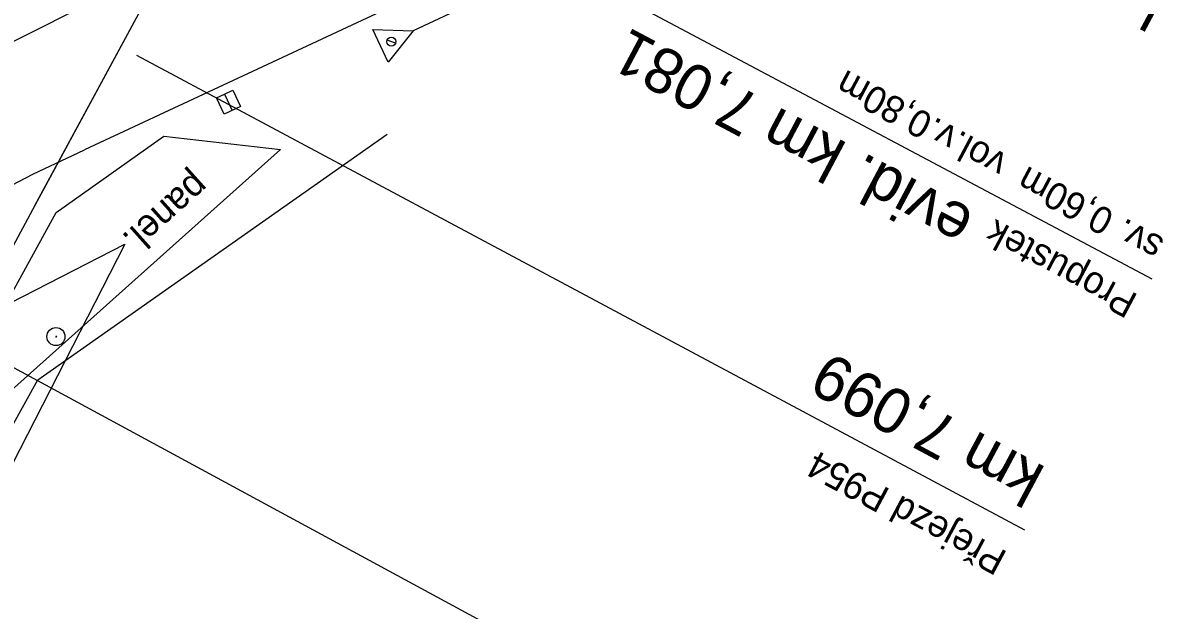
# Model space of a CAD drawing. Extents: x -795094 to -794639, y -1135368 to -1134681.
# Drawn here: x -794897.6 to -794834.2, y -1135065.2 to -1135032.7 of the extents above; entities that cross this region are included whole.
import ezdxf

# ---------------------------------------------------------------- set-up
doc = ezdxf.new("R2010")
doc.units = 0
for name, color, linetype in [('0381KM005-009P - Vrstva 1', 7, 'Continuous'), ('0381KM005-009P - Vrstva 16', 7, 'Continuous'), ('0381KM005-009P - Vrstva 17', 7, 'Continuous'), ('0381KM005-009P - Vrstva 19', 7, 'Continuous'), ('0381KM005-009P - Vrstva 3', 7, 'Continuous'), ('0381KM005-009P - Vrstva 4', 7, 'Continuous'), ('0381KM005-009P - Vrstva 43', 7, 'Continuous'), ('0381KM005-009P - Vrstva 51', 7, 'Continuous'), ('0381KM005-009P - Vrstva 7', 7, 'Continuous'), ('hran DP - hran DP', 7, 'Continuous')]:
    doc.layers.add(name, color=color, linetype=linetype)

msp = doc.modelspace()

# ---------------------------------------------------------------- linework, layer by layer
at = {"layer": '0381KM005-009P - Vrstva 1'}
msp.add_lwpolyline([(-794888.877, -1135027.929), (-794896.922, -1135042.829), (-794900.945, -1135050.279), (-794913.191, -1135072.813), (-794931.084, -1135105.636), (-794935.694, -1135114.258)], dxfattribs=at)
at = {"layer": '0381KM005-009P - Vrstva 16'}
msp.add_lwpolyline([(-794898.942, -1135053.674), (-794900.909, -1135052.62), (-794895.749, -1135043.22), (-794889.776, -1135038.979), (-794883.313, -1135039.729)], close=True, dxfattribs=at)
at = {"layer": '0381KM005-009P - Vrstva 17'}
msp.add_lwpolyline([(-794906.485, -1135078.852), (-794910.336, -1135076.942), (-794896.762, -1135052.473), (-794877.418, -1135038.884)], dxfattribs=at)
at = {"layer": '0381KM005-009P - Vrstva 19'}
msp.add_line((-794881.932, -1135021.971), (-794835.064, -1135046.885), dxfattribs=at)
at = {"layer": '0381KM005-009P - Vrstva 3'}
msp.add_line((-794900.945, -1135050.279), (-794850.198, -1135077.723), dxfattribs=at)
at = {"layer": '0381KM005-009P - Vrstva 4'}
for p, q in [((-794896.922, -1135042.829), (-794888.877, -1135027.929)), ((-794876.957, -1135033.834), (-794877.416, -1135033.663)), ((-794891.291, -1135034.505), (-794842.108, -1135060.79))]:
    msp.add_line(p, q, dxfattribs=at)
msp.add_lwpolyline([(-794872.811, -1135031.676), (-794875.963, -1135033.145), (-794877.364, -1135034.887), (-794878.213, -1135033.078), (-794875.963, -1135033.145)], dxfattribs=at)
msp.add_circle((-794877.185, -1135033.748), 0.248, dxfattribs=at)
at = {"layer": '0381KM005-009P - Vrstva 43'}
msp.add_lwpolyline([(-794886.416, -1135036.653), (-794885.963, -1135036.441), (-794885.539, -1135037.347), (-794886.445, -1135037.771), (-794886.869, -1135036.865), (-794886.416, -1135036.653), (-794885.992, -1135037.559)], dxfattribs=at)
at = {"layer": '0381KM005-009P - Vrstva 51'}
msp.add_line((-794897.036, -1135041.091), (-794894.173, -1135039.744), dxfattribs=at)
for points in [[(-794891.1, -1135030.195), (-794903.856, -1135036.615), (-794914.152, -1135043.554), (-794921.867, -1135051.409), (-794929.42, -1135063.919)], [(-794873.355, -1135030.02), (-794894.173, -1135039.744)], [(-794944.393, -1135111.84), (-794941.444, -1135105.511), (-794923.048, -1135070.462), (-794920.984, -1135065.893), (-794920.984, -1135065.893), (-794922.17, -1135065.853), (-794916.653, -1135056.999), (-794909.253, -1135049.068), (-794902.794, -1135044.104), (-794897.036, -1135041.091)]]:
    msp.add_lwpolyline(points, dxfattribs=at)
at = {"layer": '0381KM005-009P - Vrstva 7'}
msp.add_line((-794895.734, -1135050.04), (-794895.782, -1135050.128), dxfattribs=at)
msp.add_circle((-794895.758, -1135050.084), 0.5, dxfattribs=at)
at = {"layer": 'hran DP - hran DP'}
for p, q in [((-794909.29, -1135053.85), (-794891.95, -1135044.96)), ((-794891.95, -1135044.96), (-794908.62, -1135077.55))]:
    msp.add_line(p, q, dxfattribs=at)

# ---------------------------------------------------------------- texts
at = {"layer": '0381KM005-009P - Vrstva 16'}
msp.add_text('panel.', height=1.5, rotation=221.74099, dxfattribs=at).set_placement((-794888.112, -1135040.895))
at = {"layer": '0381KM005-009P - Vrstva 19'}
for s, height, p in [('evid. km 7,081', 2.5, (-794844.781, -1135043.17)), ('sv. 0,60m  vol.v.0,80m', 1.5, (-794834.291, -1135044.687)), ('Propustek', 1.5, (-794835.751, -1135047.797))]:
    msp.add_text(s, height=height, rotation=152.00625, dxfattribs=at).set_placement(p)
at = {"layer": '0381KM005-009P - Vrstva 3'}
msp.add_text('km 7,061', height=2.5, rotation=151.86217, dxfattribs=at).set_placement((-794834.01, -1135030.99))
at = {"layer": '0381KM005-009P - Vrstva 4'}
for s, height, p in [('km 7,099', 2.5, (-794840.842, -1135057.367)), ('Přejezd P954', 1.5, (-794842.992, -1135062.04))]:
    msp.add_text(s, height=height, rotation=151.87821, dxfattribs=at).set_placement(p)

doc.saveas('drawing.dxf')
